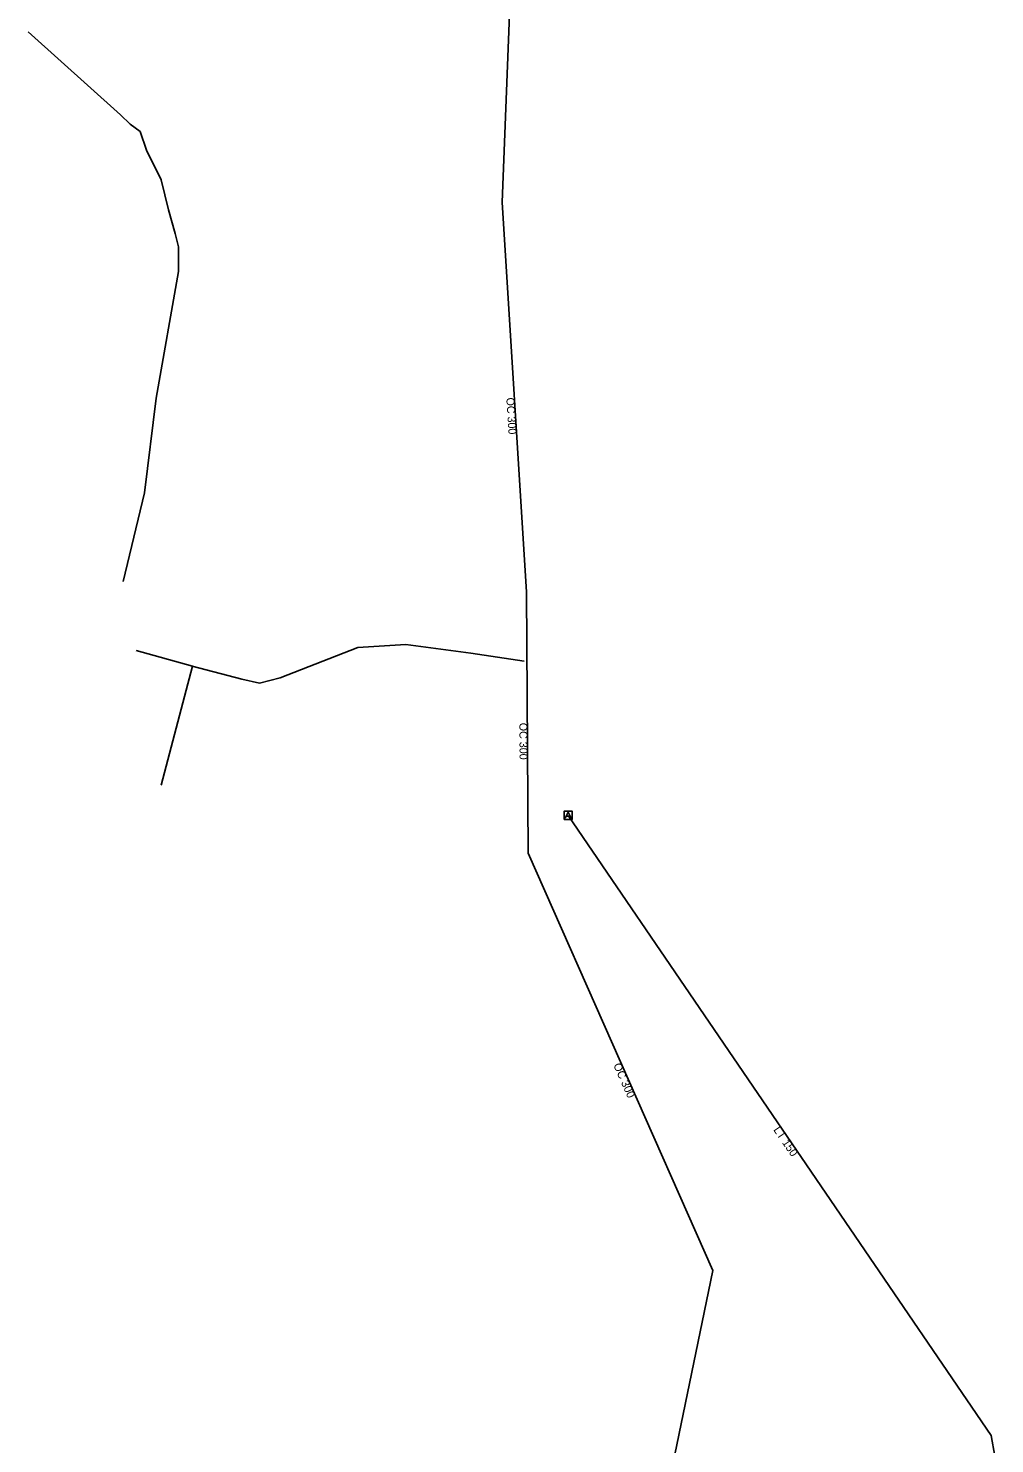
# Model space of a CAD drawing. Extents: x -513141 to -512601, y -1130827 to -1130115.
# Drawn here: x -513140.6 to -513022.8, y -1130436.4 to -1130264 of the extents above; entities that cross this region are included whole.
import ezdxf

# ---------------------------------------------------------------- set-up
doc = ezdxf.new("R2010")
doc.units = 0
for name, color, linetype in [('Default', 7, 'Continuous'), ('MoLevel 10', 7, 'Continuous'), ('MoLevel 13', 7, 'Continuous'), ('MoLevel 32', 7, 'Continuous')]:
    doc.layers.add(name, color=color, linetype=linetype)

# ---------------------------------------------------------------- blocks, each defined once
blk = doc.blocks.new('0.13')
at = {"layer": 'Default'}
for p, q in [((0, 0.04), (-0.035, -0.035)), ((0, 0.04), (0.035, -0.035)), ((-0.0235, -0.0095), (0.0235, -0.0095))]:
    blk.add_line(p, q, dxfattribs=at)
blk.add_lwpolyline([(-0.05, -0.05), (0.05, -0.05), (0.05, 0.05), (-0.05, 0.05), (-0.05, -0.05)], dxfattribs=at)

msp = doc.modelspace()

# ---------------------------------------------------------------- linework, layer by layer
at = {"layer": 'MoLevel 10'}
for p, q in [((-513081.11, -1130242.02), (-513082.81, -1130285.18)), ((-513140.55, -1130264.42), (-513129.3, -1130274.53)), ((-513129.3, -1130274.53), (-513128.12, -1130275.69)), ((-513128.12, -1130275.69), (-513126.91, -1130276.57)), ((-513126.91, -1130276.57), (-513126.16, -1130278.83)), ((-513126.16, -1130278.83), (-513124.37, -1130282.47)), ((-513124.37, -1130282.47), (-513123.45, -1130286.11)), ((-513123.45, -1130286.11), (-513122.65, -1130289)), ((-513082.81, -1130285.18), (-513079.86, -1130332.71)), ((-513122.65, -1130289), (-513122.26, -1130290.61)), ((-513122.26, -1130290.61), (-513122.26, -1130293.61)), ((-513122.26, -1130293.61), (-513124.99, -1130309.05)), ((-513124.99, -1130309.05), (-513126.39, -1130320.6)), ((-513126.39, -1130320.6), (-513128.98, -1130331.39)), ((-513079.86, -1130332.71), (-513079.64, -1130364.5)), ((-513109.86, -1130343.12), (-513100.38, -1130339.45)), ((-513100.38, -1130339.45), (-513094.53, -1130339.08)), ((-513094.53, -1130339.08), (-513086.62, -1130340.14)), ((-513127.41, -1130339.8), (-513120.56, -1130341.7)), ((-513086.62, -1130340.14), (-513080.15, -1130341.09)), ((-513120.56, -1130341.7), (-513121.52, -1130345.42)), ((-513114.54, -1130343.29), (-513120.57, -1130341.7)), ((-513109.86, -1130343.12), (-513112.39, -1130343.8)), ((-513112.39, -1130343.8), (-513114.54, -1130343.29)), ((-513121.52, -1130345.42), (-513124.35, -1130356.22)), ((-513074.77, -1130359.89), (-513023.23, -1130435.43)), ((-513079.64, -1130364.5), (-513057.15, -1130415.35)), ((-513057.15, -1130415.35), (-513063.11, -1130444.16)), ((-513023.23, -1130435.43), (-513022.8, -1130437.96))]:
    msp.add_line(p, q, dxfattribs=at)

# ---------------------------------------------------------------- block references
at = {"layer": 'MoLevel 13', "xscale": 10, "yscale": 10}
msp.add_blockref('0.13', (-513074.77, -1130359.89), dxfattribs=at)

# ---------------------------------------------------------------- texts
at = {"layer": 'MoLevel 32'}
for s, rotation, p in [('OC 300', 273.5516, (-513082.31, -1130309.01)), ('OC 300', 270.3965, (-513080.72, -1130348.61)), ('OC 300', 293.8589, (-513069.29, -1130390.32)), ('LT 150', 304.3052, (-513049.81, -1130398.21))]:
    msp.add_text(s, height=0.975, rotation=rotation, dxfattribs=at).set_placement(p)

doc.saveas('drawing.dxf')
